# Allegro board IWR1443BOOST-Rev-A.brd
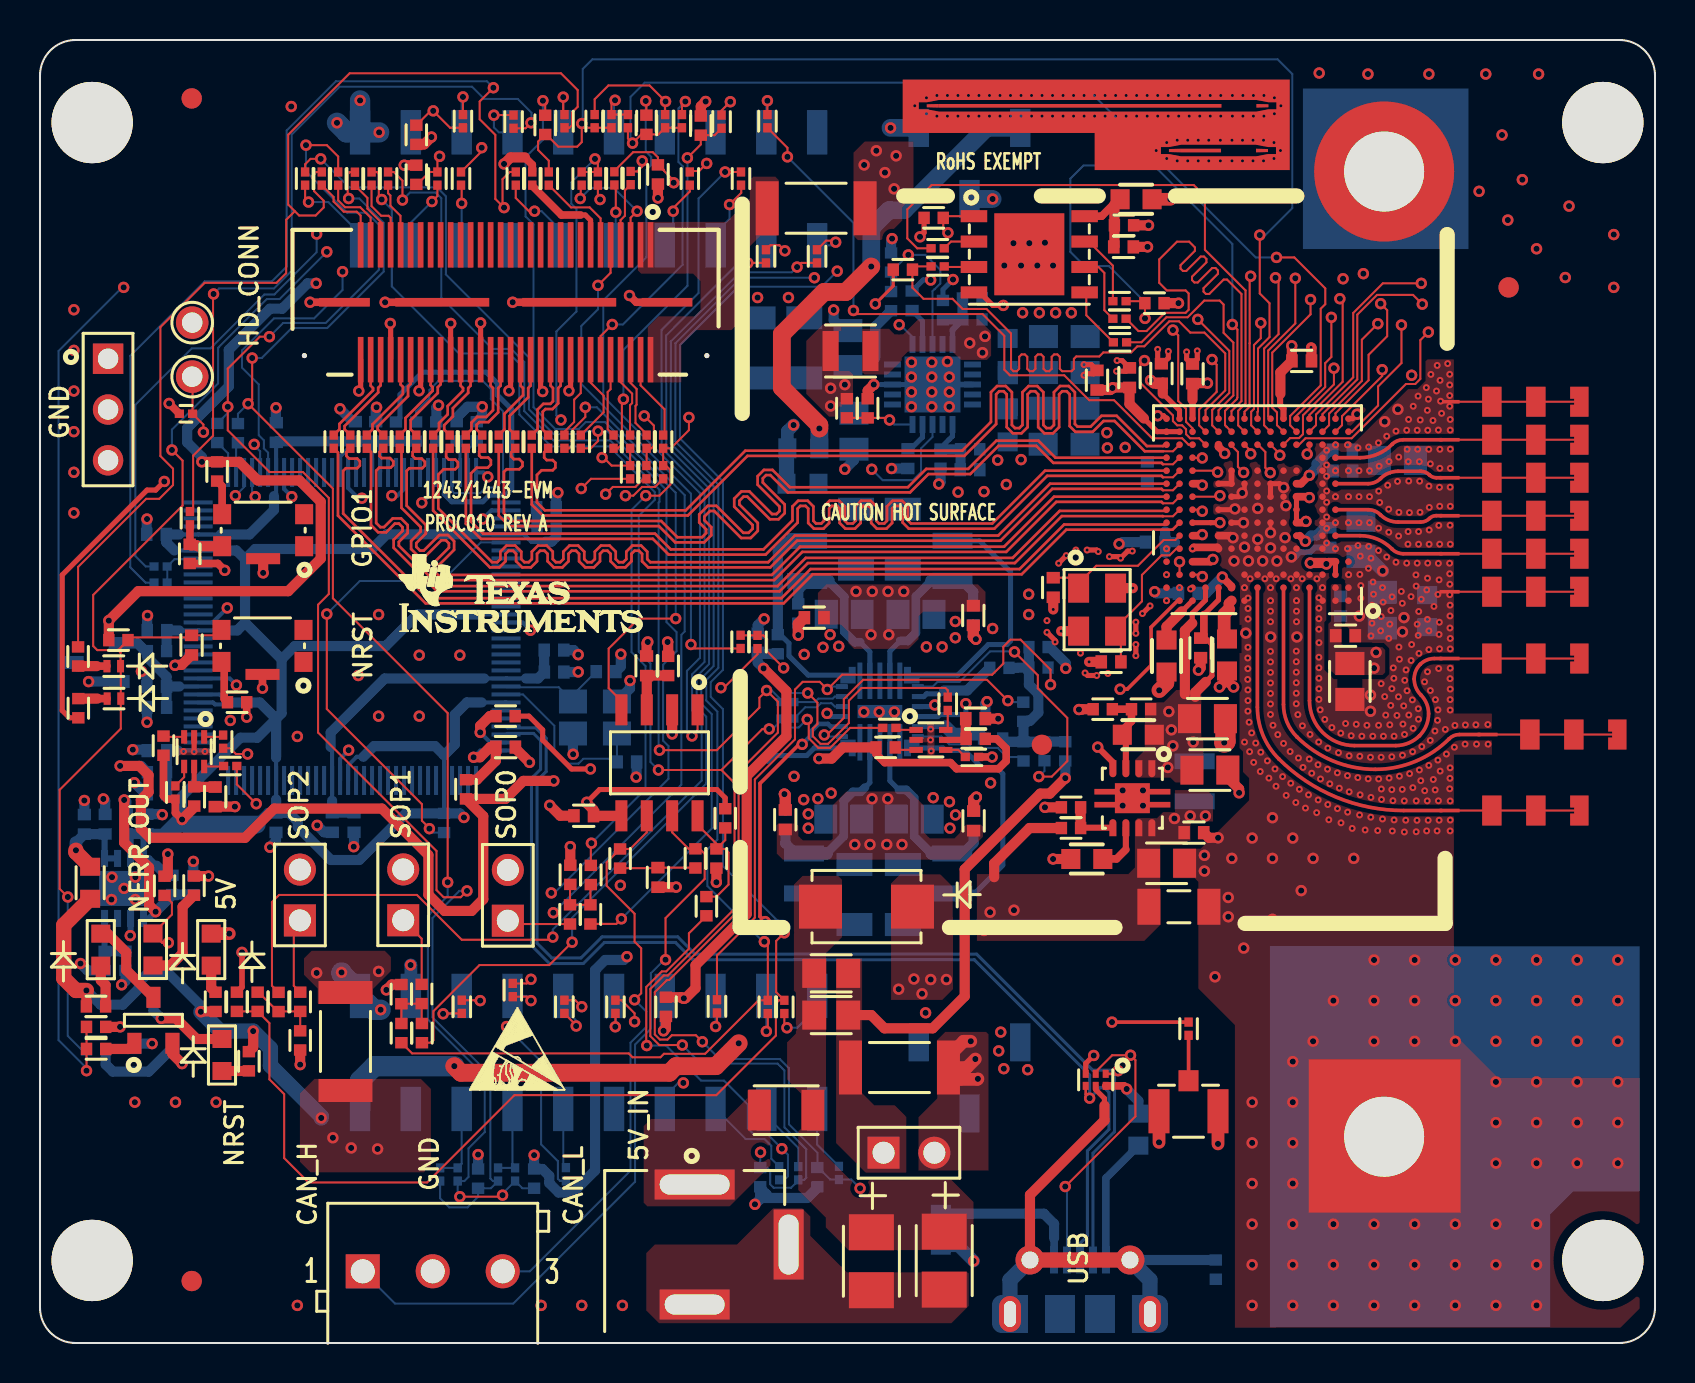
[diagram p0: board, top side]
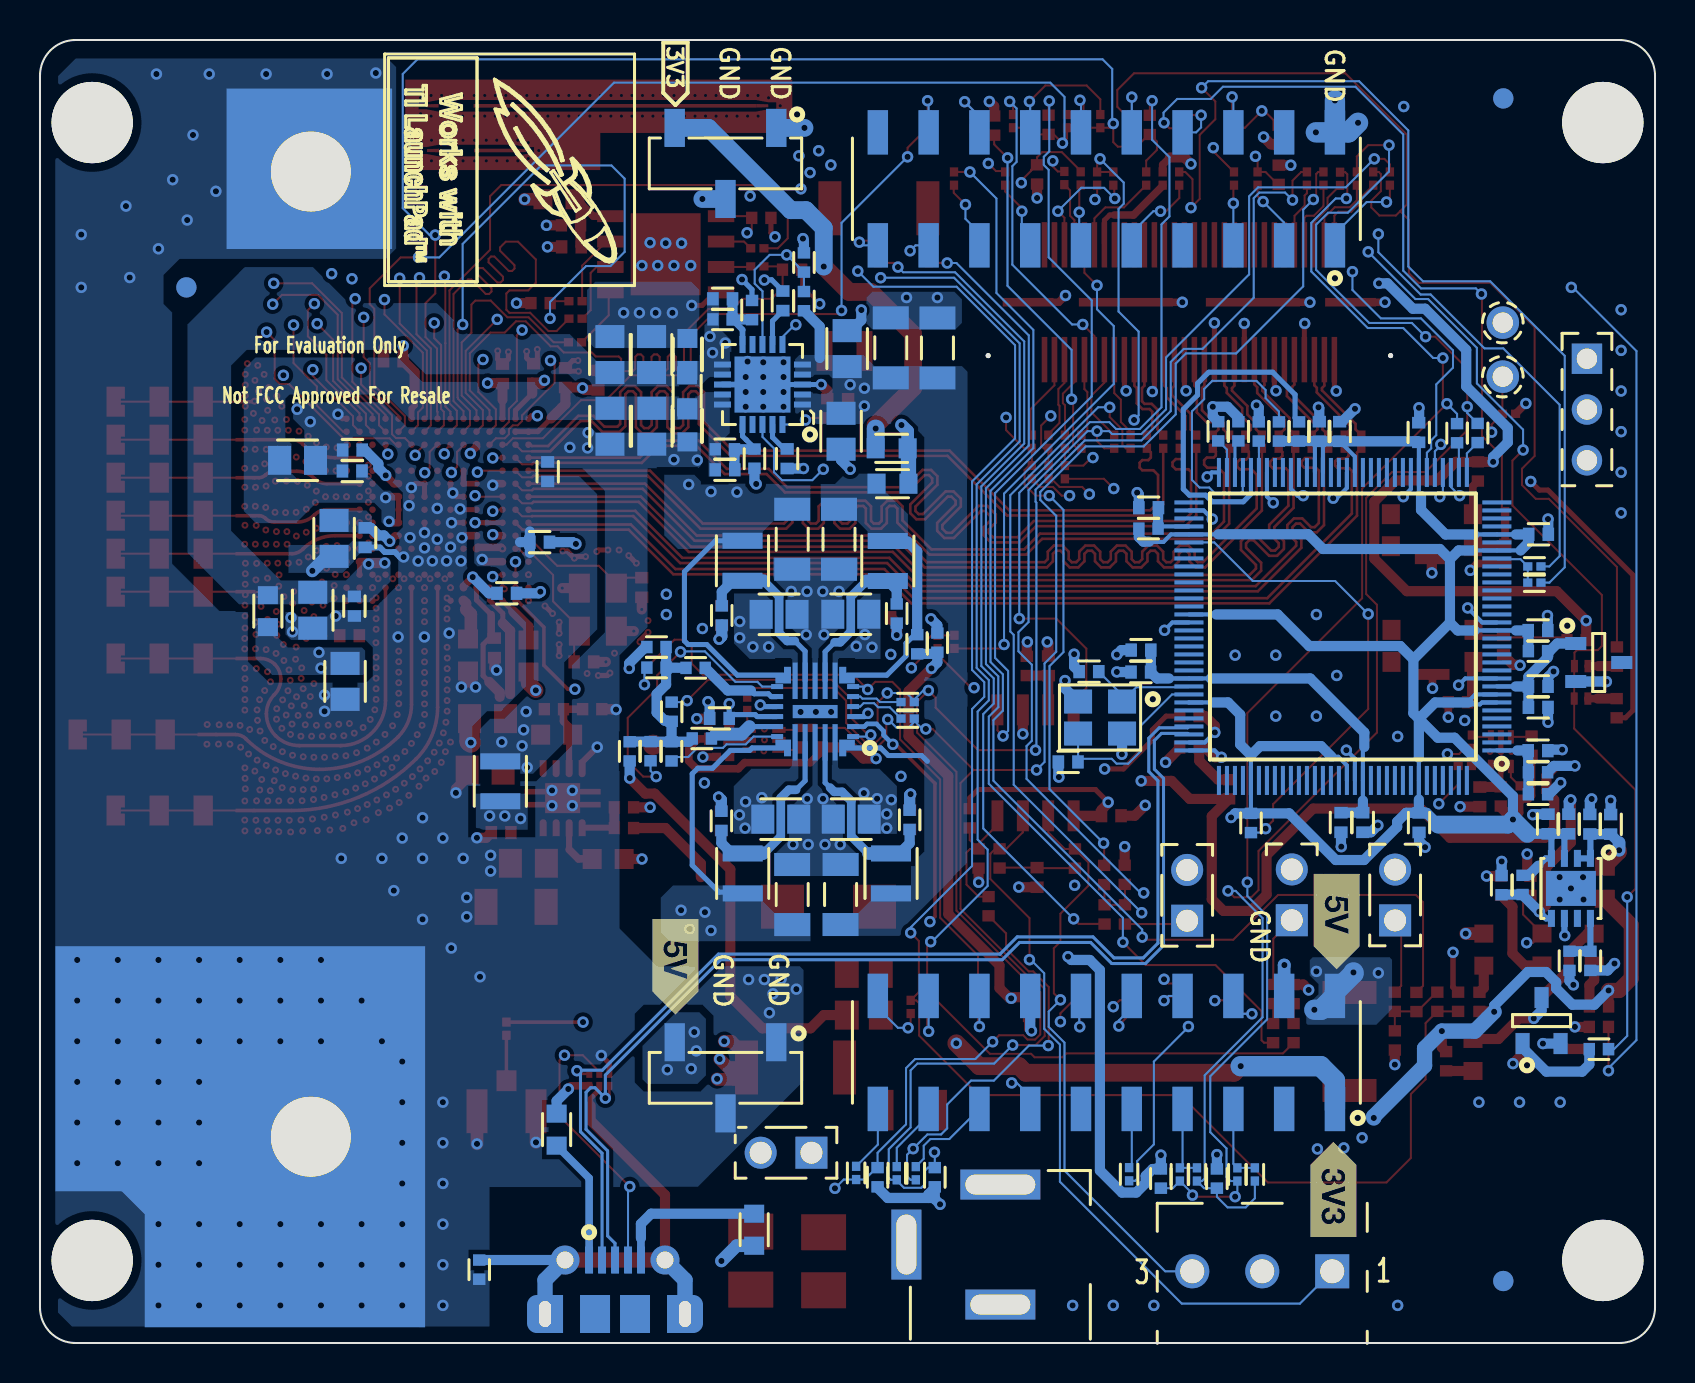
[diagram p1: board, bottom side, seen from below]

Outline 80.77 x 65.15 mm; copper layers: TOP, L2, L3, L4, L5, BOTTOM. Coordinates in mm from the lower left corner of the outline.
Outline path: 0,63.37 0,1.78 arc(0.52,0.52) 1.78,0 78.99,0 arc(80.25,0.52) 80.77,1.78 80.77,63.37 arc(80.25,64.63) 78.99,65.15 1.78,65.15 arc(0.52,64.63) 0,63.37

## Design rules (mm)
constraint set DEFAULT: min track width 0.102
net group DIFFPAIR0: nets AR_LVDS_VALIDM AR_LVDS_VALIDP
net group DIFFPAIR1: nets AR_LVDSCSI_FRCLKM AR_LVDSCSI_FRCLKP
net group DIFFPAIR2: nets AR_LVDSCSI_3M AR_LVDSCSI_3P
net group DIFFPAIR3: nets AR_LVDSCSI_2M AR_LVDSCSI_2P
net group DIFFPAIR4: nets AR_LVDSCSI_CLKM AR_LVDSCSI_CLKP
net group DIFFPAIR5: nets AR_LVDSCSI_1M AR_LVDSCSI_1P
net group DIFFPAIR6: nets AR_LVDSCSI_0M AR_LVDSCSI_0P
net group DIFFPAIR7: nets UNNAMED_6_QSH03001XD_I1_56 UNNAMED_6_QSH03001XD_I1_58
net group DIFFPAIR8: nets UNNAMED_6_QSH03001XD_I1_50 UNNAMED_6_QSH03001XD_I1_52
net group DIFFPAIR9: nets UNNAMED_6_QSH03001XD_I1_44 UNNAMED_6_QSH03001XD_I1_46
net group DIFFPAIR10: nets UNNAMED_6_QSH03001XD_I1_38 UNNAMED_6_QSH03001XD_I1_40
net group DIFFPAIR11: nets UNNAMED_6_QSH03001XD_I1_32 UNNAMED_6_QSH03001XD_I1_34
net group DIFFPAIR12: nets UNNAMED_6_QSH03001XD_I1_26 UNNAMED_6_QSH03001XD_I1_28
net group DIFFPAIR13: nets UNNAMED_6_QSH03001XD_I1_20 UNNAMED_6_QSH03001XD_I1_22
net group DIFFPAIR14: nets XDSET_1_DM XDSET_1_DP

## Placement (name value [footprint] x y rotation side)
C1  -  [CC0603]  54.82 57.19 180 top
C2  -  [CC0402]  54.19 54.81 180 top
C3  -  [CC0402]  63.1 49.11 180 top
C4  -  [CC0402]  56.09 48.48 270 top
C5  -  [CC0402]  57.64 48.46 270 top
C6  -  [CC0402]  54.49 48.27 270 top
C7  -  [CC0402]  52.87 48.14 270 top
C8  -  [CC0201]  7.3 46.46 0 top
C9  -  [CC0402]  50.68 37.78 90 top
C10  -  [CC0402]  65.29 35.37 180 top
C11  -  [CC0402]  7.58 34.89 90 top
C12  -  [CC0402]  58.05 34.75 90 top
C13  -  [CC0603]  59.36 34.4 90 top
C14  -  [CC0603]  56.34 34.35 90 top
C15  -  [CC0402]  53.57 34.06 0 top
C16  -  [CC0402]  30.34 33.86 270 top
C17  -  [CC0805]  58.39 31.22 180 top
C18  -  [CC0603]  54.93 30.41 0 top
C19  -  [CC0805]  58.51 28.65 180 top
C20  -  [CC0402]  27.19 26.36 0 top
C21  -  [CC0402]  57.71 25.52 180 top
C22  -  [CC0603]  52.35 24.2 0 top
C23  -  [CC0805]  56.35 23.99 180 top
C24  -  [CC0402]  30.91 23.28 90 top
C25  -  [CC1206]  56.96 21.81 180 top
C26  -  [CAPMP3528X210N]  45.22 4.12 270 top
C27  -  [CAPMP3528X210N]  41.58 4.09 270 top
C28  -  [CC0402]  46.63 52.21 0 bottom
C29  -  [CC0402]  43.62 52.11 270 bottom
C30  -  [CC1206]  38.22 49.76 270 bottom
C31  -  [CC1206]  35.89 49.75 270 bottom
C32  -  [CC0805]  40.4 49.72 270 bottom
C33  -  [CC0603]  48.39 49.43 270 bottom
C34  -  [CC0805]  52.27 49.42 270 bottom
C35  -  [CC0805]  50.19 49.42 270 bottom
C36  -  [CC0603]  48.39 45.86 90 bottom
C37  -  [CC0805]  50.17 45.84 90 bottom
C38  -  [CC0805]  52.27 45.84 90 bottom
C39  -  [CC0402]  65.15 44.65 180 bottom
C40  -  [CC0805]  40.71 45.59 90 bottom
C41  -  [CC0402]  16.79 45.58 270 bottom
C42  -  [CC0402]  15.77 45.58 270 bottom
C43  -  [CC0402]  11.82 45.53 270 bottom
C44  -  [CC0402]  43.41 44.22 90 bottom
C45  -  [CC0805]  67.89 44.13 0 bottom
C46  -  [CC0402]  46.51 43.66 0 bottom
C47  -  [CC0402]  65.16 43.6 180 bottom
C48  -  [CC0402]  55.38 43.57 270 bottom
C49  -  [CC0402]  25.33 41.77 180 bottom
C50  -  [CC0402]  5.83 40.43 0 bottom
C51  -  [CC0402]  64.51 40.27 90 bottom
C52  -  [CC0805]  66.06 40.23 90 bottom
C53  -  [CC0402]  55.78 40.04 0 bottom
C54  -  [CC1206]  43.15 40.19 90 bottom
C55  -  [CC1206]  40.81 40.19 90 bottom
C56  -  [CC0402]  57.43 37.49 0 bottom
C57  -  [CC0402]  65.05 36.84 90 bottom
C58  -  [CC0805]  67.13 36.64 90 bottom
C59  -  [CC0805]  40.22 36.44 180 bottom
C60  -  [CC0805]  43.81 36.43 0 bottom
C61  -  [CC0402]  5.85 35.63 0 bottom
C62  -  [CC0402]  25.71 34.65 180 bottom
C63  -  [CC0402]  28.31 33.57 180 bottom
C64  -  [CC0402]  25.71 33.55 180 bottom
C65  -  [CC0805]  65.52 33.08 90 bottom
C66  -  [CC0402]  5.84 32.83 0 bottom
C67  -  [CC0402]  5.84 31.78 0 bottom
C68  -  [CC0402]  46.79 31.23 180 bottom
C69  -  [CC0402]  5.85 29.62 0 bottom
C70  -  [CC0402]  29.35 29.06 180 bottom
C71  -  [CC0402]  23.29 29.79 180 top
C72  -  [CC0805]  43.72 26.19 0 bottom
C73  -  [CC0805]  40.2 26.19 180 bottom
C74  -  [CC0402]  15.71 26.03 90 bottom
C75  -  [CC0402]  14.62 26.03 90 bottom
C76  -  [CC0402]  11.8 26.02 90 bottom
C77  -  [CC0402]  5.35 25.95 270 bottom
C78  -  [CC0402]  4.31 25.95 270 bottom
C79  -  [CC0402]  3.26 25.94 270 bottom
C80  -  [CC0402]  2.22 25.93 270 bottom
C81  -  [CC1206]  40.73 22.43 270 bottom
C82  -  [CC1206]  43.15 22.42 270 bottom
C83  -  [CC0805]  65.51 33.07 90 top
C84  -  [CC0402]  46.79 31.22 180 top
C85  -  [CC0402]  8.76 27.31 90 top
C86  -  [CC0402]  38.72 36.27 180 top
C87  -  [CC0402]  46.68 36.38 270 top
C88  -  [CC0402]  37.27 26.17 90 top
C89  -  [CC0402]  46.69 26.11 90 top
D1  -  [DFN100X60X50-2N]  3.69 33.84 0 top
D2  -  [DFN100X60X50-2N]  3.7 32.22 0 top
D3  -  [DIOM5436X295N]  41.34 21.82 0 top
DS1  -  [LED0603]  5.65 19.68 270 top
DS2  -  [LED0603]  8.56 19.67 270 top
DS3  -  [LED0603]  3.04 19.67 270 top
DS4  -  [LED0603]  9.1 14.4 270 top
F1  -  [FUSE1206]  37.32 11.64 0 top
FB1  -  [FB0805]  39.57 16.4 0 top
FB2  -  [FB0805]  39.57 18.48 0 top
J1  -  [SAMTEC_QSH-030-01-X-D-A]  23.29 52.04 180 top
J2  -  [CINCH_128-0711-201]  57.44 11.59 90 top
J3  -  [OST_OSTTE030161]  16.14 3.59 0 top
J4  -  [SAMTEC_SSM-103-XX-SV]  46.49 58.98 0 bottom
J5  -  [SAMTEC_SSM-110-XX-DV]  27.44 57.71 180 bottom
J6  -  [SAMTEC_SSM-110-XX-DV]  27.44 14.53 180 bottom
J7  -  [SAMTEC_SSM-103-XX-SV]  46.49 13.26 0 bottom
J8  -  [MOLEX_105017-0001]  52.01 1.6 180 bottom
L1  -  [INDC2520X120N]  45.64 39.11 90 bottom
L2  -  [INDC2520X120N]  38.37 39.1 270 bottom
L3  -  [INDC2520X120N]  45.63 23.48 270 bottom
L4  -  [INDC2520X120N]  38.21 23.48 90 bottom
L5  -  [INDC2520X120N]  40.54 49.6 0 top
L6  -  [INDC2520X120N]  57.75 28.09 90 bottom
NOREF  -  []  3.19 33.54 0 top
NOREF#2  -  []  14.74 60.25 0 top
NOREF#3  -  []  46.64 46.93 90 top
NOREF#4  -  []  8.61 28.83 90 top
NOREF#5  -  []  7.13 15.46 90 top
NOREF#6  -  []  48.51 1.45 90 top
NOREF#7  -  []  8.16 18.87 0 top
NOREF#8  -  []  39.04 21.82 0 top
NOREF#9  -  []  55.69 46.87 0 top
NOREF#10  -  []  52.66 4.15 0 top
NOREF#11  -  []  43.95 60.76 0 top
NOREF#12  -  []  6.62 14.99 90 top
NOREF#13  -  []  4.72 14.97 0 top
NOREF#14  -  []  8.39 48.54 0 top
NOREF#15  -  []  12.63 48.42 0 top
NOREF#16  -  []  53.66 25.77 90 top
NOREF#17  -  []  8.61 42.83 0 top
NOREF#18  -  []  3.04 18.87 90 top
NOREF#19  -  []  3.36 32.22 0 top
NOREF#20  -  []  37.21 22.23 90 top
NOREF#21  -  []  26.15 30.02 90 top
NOREF#22  -  [unnamed#2]  67.23 58.57 0 top
NOREF#23  -  []  5.65 18.88 90 top
NOREF#24  -  []  14.74 55.17 90 top
NOREF#25  -  []  5.18 21.23 90 top
NOREF#26  -  []  36.33 11.7 0 top
NOREF#27  -  []  43.64 49.93 0 top
NOREF#28  -  []  2.64 18.87 0 top
NOREF#29  -  []  4.21 16.8 0 top
NOREF#30  -  [unnamed#3]  78.16 61.02 0 top
NOREF#31  -  []  39.37 40.35 90 top
NOREF#32  -  []  3.23 24.23 0 top
NOREF#33  -  []  8.39 51.25 0 top
NOREF#34  -  []  14.74 11.99 90 top
NOREF#35  -  []  15.23 52.04 0 top
NOREF#36  -  [unnamed#2]  50.11 29.91 0 top
NOREF#37  -  []  3.44 18.87 90 top
NOREF#38  -  []  40.92 8.24 0 top
NOREF#39  -  []  18.17 21.14 90 top
NOREF#40  -  []  52.08 12.66 0 top
NOREF#41  -  []  42.68 11.99 0 top
NOREF#42  -  []  55.76 -1.1 90 top
NOREF#43  -  []  6.05 18.88 90 top
NOREF#44  -  []  41.01 30.03 0 top
NOREF#45  -  []  38.21 22.48 90 top
NOREF#46  -  [unnamed#3]  2.61 61.02 0 top
NOREF#47  -  [unnamed#2]  73.45 52.78 0 top
NOREF#48  -  [unnamed#3]  78.16 4.13 0 top
NOREF#49  -  []  8.56 18.87 90 top
NOREF#50  -  []  54.96 28.72 0 top
NOREF#51  -  []  4.19 33.54 90 top
NOREF#52  -  []  9.08 34.06 90 top
NOREF#53  -  []  2.71 21.23 90 top
NOREF#54  -  []  5.67 17.29 0 top
NOREF#55  -  []  46.63 22.23 90 top
NOREF#56  -  []  8.7 13.6 0 top
NOREF#57  -  []  13.22 49.37 0 top
NOREF#58  -  [unnamed#2]  67.23 10.31 0 top
NOREF#59  -  []  37.37 42.85 0 top
NOREF#60  -  []  41.79 48.6 90 top
NOREF#61  -  []  9.11 39.84 0 top
NOREF#62  -  []  16.04 49.17 0 top
NOREF#63  -  []  44.64 40.36 0 top
NOREF#64  -  []  16.04 49.17 90 top
NOREF#65  -  []  19.44 19.87 90 top
NOREF#66  -  []  9.5 13.6 90 top
NOREF#67  -  []  23.31 32.03 90 top
NOREF#68  -  []  39.29 48.6 0 top
NOREF#69  -  []  28.24 -5.78 0 top
NOREF#70  -  []  46.63 53.8 90 top
NOREF#71  -  []  44.06 20.01 90 top
NOREF#72  -  []  52.48 51.94 90 top
NOREF#73  -  []  3.4 46.67 90 top
NOREF#74  -  []  9.08 34.06 0 top
NOREF#75  -  [unnamed#3]  2.61 4.13 0 top
NOREF#76  -  []  44.64 37.86 90 top
NOREF#77  -  []  33.94 48.42 90 top
NOREF#78  -  []  38.61 20.01 0 top
NOREF#79  -  []  4.21 15.47 90 top
NOREF#80  -  []  56.75 26.84 90 top
NOREF#81  -  []  32.74 7.92 0 top
NOREF#82  -  []  26.65 32.07 0 top
NOREF#83  -  []  4.2 31.92 90 top
NOREF#84  -  []  38.37 38.1 90 top
NOREF#85  -  []  3.2 31.92 0 top
NOREF#86  -  []  50.3 11.99 90 top
NOREF#87  -  []  56.75 29.34 0 top
NOREF#88  -  []  40.01 33.82 0 top
NOREF#89  -  []  55.97 11.59 0 top
NOREF#90  -  []  14.27 19.86 90 top
NOREF#91  -  []  2.16 42.86 90 top
NOREF#92  -  []  4.72 14.97 90 top
NOREF#93  -  []  3.35 33.84 0 top
NOREF#94  -  []  55.69 36.47 90 top
NOREF#95  -  []  22.13 19.84 0 top
NOREF#96  -  []  42.19 9.51 0 top
NOREF#97  -  []  24.67 19.84 90 top
NOREF#98  -  []  46.63 52.53 0 top
NOREF#99  -  []  9.06 42.04 0 top
NOREF#100  -  []  45.63 22.48 90 top
NOREF#101  -  []  13 21.13 90 top
NOREF#102  -  []  0 63.37 0 top
NOREF#103  -  []  11.73 19.86 0 top
NOREF#104  -  []  55.94 10.29 90 top
NOREF#105  -  []  52.8 12.86 0 top
NOREF#106  -  []  56.13 25.74 90 top
NOREF#107  -  []  42.64 53.93 0 top
NOREF#108  -  []  39.54 49.6 0 top
NOREF#109  -  []  51.62 38.27 0 top
NOREF#110  -  []  50.3 57.71 90 top
NOREF#111  -  []  40.01 33.82 90 top
NOREF#112  -  []  37.24 -5.78 90 top
NOREF#113  -  []  54.12 35.07 90 top
NOREF#114  -  []  9.1 13.6 90 top
NOREF#115  -  []  23.4 21.11 90 top
NOREF#116  -  []  4.21 16.78 0 top
NOREF#117  -  []  2.16 50.48 0 top
NOREF#118  -  []  37.21 24.73 0 top
NOREF#119  -  []  78.99 0 90 top
NOREF#120  -  []  24.54 54.91 0 top
NOREF#121  -  []  36.33 54.88 0 top
NOREF#122  -  []  57.75 27.09 90 top
NOREF#123  -  []  55.94 12.89 0 top
NOREF#124  -  []  42.68 57.71 0 top
NOREF#125  -  []  43.95 15.04 0 top
NOREF#126  -  []  24.89 -0.01 90 top
NOREF#127  -  []  32.74 1.92 90 top
NOREF#128  -  []  26.15 30.02 0 top
NOREF#129  -  []  44.63 22.23 0 top
NOREF#130  -  []  45.64 38.11 90 top
NOREF#131  -  []  40.92 8.24 90 top
NOREF#132  -  []  52.08 13.66 0 top
NOREF#133  -  []  42.64 49.93 90 top
NOREF#134  -  []  5.25 18.88 0 top
NOREF#135  -  []  9.11 39.84 90 top
NOREF#136  -  []  16.9 19.87 0 top
NOREF#137  -  [unnamed#2]  7.59 3.1 0 top
NOREF#138  -  []  65.44 39.07 90 top
NOREF#139  -  []  51.94 35.59 90 top
NOREF#140  -  [unnamed#2]  7.59 62.23 0 top
NOREF#141  -  []  43.6 29.75 90 top
NOREF#142  -  []  13.23 30.66 0 top
NOREF#143  -  []  14.74 17.07 0 top
NOREF#144  -  []  19.64 3.59 0 top
NOREF#145  -  []  8.96 18.87 90 top
NOREF#146  -  []  48.51 1.45 0 top
NOREF#147  -  [unnamed#2]  73.45 52.78 180 bottom
NOREF#148  -  [unnamed#2]  7.59 3.1 180 bottom
NOREF#149  -  [unnamed#2]  7.59 62.23 180 bottom
P1  -  [MOLEX_22-28-4033]  3.4 49.21 0 top
P2  -  [MULTICOMP_2211S-02G]  18.17 21.14 90 top
P3  -  [MULTICOMP_2211S-02G]  13 21.13 90 top
P4  -  [MULTICOMP_2211S-02G]  23.4 21.11 90 top
P5  -  [MULTICOMP_2211S-02G]  42.19 9.51 0 top
P6  -  [CUI_PJ-002AH]  32.74 7.92 0 top
Q1  -  [SOT95P240X120-3N]  5.67 16.14 90 top
Q2  -  [SOT95P240X120-3N]  5.67 16.12 90 bottom
R1  -  [RC0201]  21.15 61.09 270 top
R2  -  [RC0201]  26.23 61.09 270 top
R3  -  [RC0201]  27.74 61.09 270 top
R4  -  [RC0201]  28.58 61.09 270 top
R5  -  [RC0201]  29.4 61.09 270 top
R6  -  [RC0201]  31.26 61.09 270 top
R7  -  [RC0201]  32.11 61.09 270 top
R8  -  [RC0201]  36.38 61.09 270 top
R9  -  [RC0201]  23.69 61.07 270 top
R10  -  [RC0201]  34.09 61.07 270 top
R11  -  [RC0402]  30.33 60.91 90 top
R12  -  [RC0402]  25.27 60.91 90 top
R13  -  [RC0402]  33.05 60.87 270 top
R14  -  [RC0402]  18.82 60.41 270 top
R15  -  [RC0402]  30.91 58.43 270 top
R16  -  [RC0402]  18.82 58.41 90 top
R17  -  [RC0201]  29.54 58.25 270 top
R18  -  [RC0201]  28.73 58.23 270 top
R19  -  [RC0201]  13.26 58.22 270 top
R20  -  [RC0201]  14.09 58.22 270 top
R21  -  [RC0201]  14.91 58.22 270 top
R22  -  [RC0201]  16.58 58.22 270 top
R23  -  [RC0201]  17.41 58.22 270 top
R24  -  [RC0201]  19.88 58.22 270 top
R25  -  [RC0201]  21.06 58.22 270 top
R26  -  [RC0201]  23.8 58.22 270 top
R27  -  [RC0201]  24.62 58.22 270 top
R28  -  [RC0201]  25.45 58.22 270 top
R29  -  [RC0201]  27.09 58.22 270 top
R30  -  [RC0201]  27.9 58.22 270 top
R31  -  [RC0201]  32.5 58.22 270 top
R32  -  [RC0201]  35.06 58.22 270 top
R33  -  [RC0201]  15.75 58.21 270 top
R34  -  [RC2010]  38.82 56.74 0 top
R35  -  [RC0201]  36.31 54.34 90 top
R36  -  [RC0201]  38.86 54.34 90 top
R37  -  [RC0402]  54.22 55.89 0 top
R38  -  [RC0402]  44.7 56.26 180 top
R39  -  [RC0201]  44.9 54.74 0 top
R40  -  [RC0201]  53.99 52.09 0 top
R41  -  [RC0402]  55.74 51.99 0 top
R42  -  [RC0201]  44.9 53.83 0 top
R43  -  [RC0402]  43.16 53.67 180 top
R44  -  [RC0201]  53.99 51.22 0 top
R45  -  [RC0201]  54.01 50.03 0 top
R46  -  [RC0402]  40.36 46.74 270 top
R47  -  [RC0402]  41.4 46.74 90 top
R48  -  [RC0201]  14.69 45.07 270 top
R49  -  [RC0201]  15.52 45.07 270 top
R50  -  [RC0201]  16.34 45.07 270 top
R51  -  [RC0201]  17.17 45.07 270 top
R52  -  [RC0201]  18 45.07 270 top
R53  -  [RC0201]  18.82 45.07 270 top
R54  -  [RC0201]  19.66 45.07 270 top
R55  -  [RC0201]  20.49 45.07 270 top
R56  -  [RC0201]  21.3 45.07 270 top
R57  -  [RC0201]  22.12 45.07 270 top
R58  -  [RC0201]  22.94 45.07 270 top
R59  -  [RC0201]  23.77 45.07 270 top
R60  -  [RC0201]  24.59 45.07 270 top
R61  -  [RC0201]  25.41 45.07 270 top
R62  -  [RC0201]  26.23 45.07 270 top
R63  -  [RC0201]  27.05 45.07 270 top
R64  -  [RC0201]  28.69 45.07 270 top
R65  -  [RC0201]  29.51 45.07 270 top
R66  -  [RC0201]  30.34 45.07 270 top
R67  -  [RC0201]  31.17 45.07 270 top
R68  -  [RC0402]  8.86 43.58 90 top
R69  -  [RC0201]  29.51 43.54 270 top
R70  -  [RC0201]  30.33 43.54 270 top
R71  -  [RC0201]  31.17 43.54 270 top
R72  -  [RC0201]  7.5 41.24 90 top
R73  -  [RC0402]  7.49 39.46 90 top
R74  -  [RC0402]  3.92 35.14 180 top
R75  -  [RC0201]  35.04 35.06 270 top
R76  -  [RC0201]  35.88 35.05 270 top
R77  -  [RC0402]  1.91 34.32 270 top
R78  -  [RC0402]  31.42 33.85 90 top
R79  -  [RC0402]  9.86 32.04 180 top
R80  -  [RC0402]  1.92 31.74 90 top
R81  -  [RC0402]  53.15 31.69 0 top
R82  -  [RC0402]  55.07 31.69 0 top
R83  -  [RC0402]  51.56 26.78 180 top
R84  -  [RC0402]  51.56 25.75 0 top
R85  -  [RC0402]  32.78 24.23 90 top
R86  -  [RC0402]  33.83 24.22 270 top
R87  -  [RC0402]  29.01 24.22 270 top
R88  -  [RC0402]  26.52 23.41 270 top
R89  -  [RC0402]  27.55 23.4 270 top
R90  -  [RC0402_40]  7.7 22.87 90 top
R91  -  [RC0402]  6.23 22.86 90 top
R92  -  [RC0402]  26.51 21.43 270 top
R93  -  [RC0402]  27.53 21.43 270 top
R94  -  [RC0201]  23.65 17.65 90 top
R95  -  [RC0402]  19.09 17.45 90 top
R96  -  [RC0402]  18.07 17.44 270 top
R97  -  [RC0402]  9.85 17.06 90 top
R98  -  [RC0402]  10.89 17.06 90 top
R99  -  [RC0402]  13.01 17.06 90 top
R100  -  [RC0402]  8.78 17.06 270 top
R101  -  [RC0402]  11.93 17.05 90 top
R102  -  [RC0201]  33.86 16.83 90 top
R103  -  [RC0402]  2.8 16.83 180 top
R104  -  [RC0201]  21.09 16.81 90 top
R105  -  [RC0201]  26.23 16.81 90 top
R106  -  [RC0201]  28.78 16.81 90 top
R107  -  [RC0402]  31.31 16.81 90 top
R108  -  [RC0201]  36.4 16.8 90 top
R109  -  [RC0201]  37.23 16.8 90 top
R110  -  [RC0402]  2.81 15.81 180 top
R111  -  [RC0201]  57.44 15.71 270 top
R112  -  [RC0402]  19.1 15.5 270 top
R113  -  [RC0402]  18.08 15.5 90 top
R114  -  [RC0402]  13.01 15.13 90 top
R115  -  [RC2010]  15.28 15.08 270 top
R116  -  [RC0402]  2.81 14.7 0 top
R117  -  [RC0402]  10.45 14.09 90 top
R118  -  [RC2010]  42.98 13.77 0 top
R119  -  [RC0402]  42.56 54.03 270 bottom
R120  -  [RC0402]  42.56 52.1 270 bottom
R121  -  [RC0402]  45.16 51.65 270 bottom
R122  -  [RC0402]  46.64 51.18 0 bottom
R123  -  [RC0402]  21.84 45.58 90 bottom
R124  -  [RC0402]  18.81 45.58 270 bottom
R125  -  [RC0402]  19.82 45.58 270 bottom
R126  -  [RC0402]  20.84 45.58 90 bottom
R127  -  [RC0402]  17.8 45.58 270 bottom
R128  -  [RC0402]  8.87 45.5 270 bottom
R129  -  [RC0402]  9.9 45.49 270 bottom
R130  -  [RC0603]  38.18 44.73 180 bottom
R131  -  [RC0402]  46.52 44.69 0 bottom
R132  -  [RC0402]  45.04 44.22 90 bottom
R133  -  [RC0603]  38.14 42.97 180 bottom
R134  -  [RC0402]  25.33 40.72 0 bottom
R135  -  [RC0201]  6.03 38.83 0 bottom
R136  -  [RC0201]  6.03 38.02 0 bottom
R137  -  [RC0603]  69.38 36.59 270 bottom
R138  -  [RC0402]  35.89 35.02 270 bottom
R139  -  [RC0402]  49.94 34.8 180 bottom
R140  -  [RC0402]  5.85 34.6 0 bottom
R141  -  [RC0402]  36.9 34.94 270 bottom
R142  -  [RC0402]  49.94 33.77 180 bottom
R143  -  [RC0402]  47.98 33.76 0 bottom
R144  -  [RC0201]  37.38 32.05 0 bottom
R145  -  [RC0402]  49.18 31.56 270 bottom
R146  -  [RC0201]  37.38 31.22 0 bottom
R147  -  [RC0402]  47.67 30.23 0 bottom
R148  -  [RC0402]  50.23 29.59 90 bottom
R149  -  [RC0402]  51.28 29.58 270 bottom
R150  -  [RC0402]  49.19 29.58 270 bottom
R151  -  [RC0402]  5.85 28.54 0 bottom
R152  -  [RC0402]  23.29 31.34 0 top
R153  -  [RC0402]  5.85 27.44 0 bottom
R154  -  [RC0402]  21.3 27.69 270 top
R155  -  [RC0402]  20.21 26 90 bottom
R156  -  [RC0402]  6.62 22.9 90 bottom
R157  -  [RC0402_40]  7.67 22.89 270 bottom
R158  -  [RC0402]  4.28 19.11 90 bottom
R159  -  [RC0402]  3.23 19.11 90 bottom
R160  -  [RC0402]  2.81 14.69 0 bottom
R161  -  [RC0603]  54.93 10.67 90 bottom
R162  -  [RC0201]  39.95 8.5 90 bottom
R163  -  [RC0201]  37.92 8.49 90 bottom
R164  -  [RC0201]  36.97 8.49 90 bottom
R165  -  [RC0201]  26.3 8.44 90 bottom
R166  -  [RC0201]  23.76 8.43 90 bottom
R167  -  [RC0201]  22.91 8.43 90 bottom
R168  -  [RC0201]  20.89 8.43 90 bottom
R169  -  [RC0201]  20.01 8.43 90 bottom
R170  -  [RC0402]  38.88 8.29 270 bottom
R171  -  [RC0402]  36.02 8.29 270 bottom
R172  -  [RC0402]  24.71 8.22 90 bottom
R173  -  [RC0402]  21.91 8.22 90 bottom
R174  -  [RC0402_40]  58.8 3.67 90 bottom
R175  -  [RC0603]  45.05 5.66 90 bottom
R176  -  [RC0603]  2.51 23.01 270 top
R177  -  [RC0402]  33.33 21.84 270 top
R178  -  [RC0402]  34.27 26.23 270 top
R179  -  [RC0402]  42.29 29.78 180 top
R180  -  [RC0201]  42.48 30.76 0 top
R181  -  [RC0201]  46.61 29.3 180 top
R182  -  [RC0201]  45.4 31.96 90 top
R183  -  [RC0402]  46.8 30.21 0 top
R184  -  [RC0402]  6.18 29.87 270 top
R185  -  [RC0201]  9.16 30.07 90 top
R186  -  [RC0201]  9.51 28.85 0 top
R187  -  [RC0402]  7.71 27.33 270 top
R188  -  [RC0201]  6.77 27.53 270 top
R189  -  [RC0603]  48.41 47.59 270 bottom
R190  -  [RC0402]  37.92 36.47 90 bottom
R191  -  [RC0402]  46.67 36.38 90 bottom
R192  -  [RC0402]  37.28 26.16 270 bottom
R193  -  [RC0402]  46.69 26.11 270 bottom
SW1  -  [SW_KMR2XXG]  11.16 40.64 180 top
SW2  -  [SW_KMR2XXG]  11.13 34.86 180 top
TP1  -  [TP_C163H102]  7.61 51.02 0 top
TP2  -  [TP_C163H102]  7.61 48.32 0 top
U1  -  [SON127P600X500X80_EPA-9N]  49.48 54.44 0 top
U2  -  [BGA161C65P15X15_1040X1040X120]  60.89 41.67 180 top
U3  -  [SOIC127P600X175-8N]  30.98 29.01 270 top
U4  -  [SON65P300X300X100-9]  54.63 27.24 270 top
U5  -  [QFN50P400X400X80_EPE-21N]  44.64 47.93 0 bottom
U6  -  [QFP40P1600X1600X120-128N]  15.61 35.83 0 bottom
U7  -  [SOT95P237X112-3N]  2.82 34.03 180 bottom
U8  -  [P87524BRNFRQ1_ES2_2_PRELIMINARY]  42.01 31.57 0 bottom
U9  -  [SON65P300X300X100_EPA-9N]  4.21 22.73 270 bottom
U10  -  [PSON50P100X145X60-6N]  52.8 13.16 270 top
U11  -  [SOTFL50P160X60-6N]  44.56 30.16 0 top
U12  -  [SOTFL50P160X60-6N]  7.71 29.57 270 top
Y1  -  [XTAL_CX3225SA]  52.87 36.67 270 top
Y2  -  [XTAL_NX3225SA]  27.75 31.27 0 bottom

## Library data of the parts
C1 C13 C14 C33 C36 = CAP_NON_POLARIZED: alternate symbols: (); part number: CAP_NON_POLARIZED_0603-GCM188R71C105KA64,1UF,10%
C2 C21 = CAP_NON_POLARIZED: alternate symbols: (); part number: CAP_NON_POLARIZED_0402-CGA2B3X7R1H104K050BB,0.1UF,10%
C3 C5 C7 C10 C12 C39 C47 C48 C51 C53 C56 C57 C68 = CAP_NON_POLARIZED: alternate symbols: (); part number: CAP_NON_POLARIZED_0402-GCM155R71C224KE02,0.22UF,10%
C4 C6 C11 = CAP_NON_POLARIZED: alternate symbols: (); part number: CAP_NON_POLARIZED_0402-GCM155R71C104KA55,0.1UF,10%
C8 = CAP_NON_POLARIZED: alternate symbols: (); part number: CAP_NON_POLARIZED_0201-C0603X7S1A104K030BC,0.1UF,10%
C9 C15 C24 = CAP_NON_POLARIZED: alternate symbols: (); part number: CAP_NON_POLARIZED_0402-GJM1555C1H4R7BB01,4.7PF,+/-0.1PF
C16 C20 C42 C43 C49 C64 C67 C71 C75 C76 C79 C84 C85 = CAP_NON_POLARIZED: alternate symbols: (); part number: CAP_NON_POLARIZED_0402-C0402C104K8RAC,0.1UF,10%
C17 C19 C23 C32 C34 C35 C37 C38 C40 C45 C52 C58-C60 C65 C72 C73 C83 = CAP_NON_POLARIZED: alternate symbols: (CAP_GC_21); part number: CAP_NON_POLARIZED_0805-GCM21BR71A106KE22,10UF,10%
C18 C22 = CAP_NON_POLARIZED: alternate symbols: (); part number: CAP_NON_POLARIZED_0603-GCM188R71C474KA55,0.47UF,10%
C25 C30 C31 = CAP_NON_POLARIZED: alternate symbols: (); part number: CAP_NON_POLARIZED_1206-CGA5L1X7R0J226M160AC,22UF,20%
C26 C27 = CAP_POLARIZED: alternate symbols: (); part number: CAP_POLARIZED_3528-21-T491B476K010AT,47UF,10%
C28 C29 C44 C46 = CAP_NON_POLARIZED: alternate symbols: (); part number: CAP_NON_POLARIZED_0402-CGA2B3X8R1H103K050BB,0.01UF,10%
C41 C61 C62 = CAP_NON_POLARIZED: alternate symbols: (); part number: CAP_NON_POLARIZED_0402-C1005X7S0J105M050BC,1UF,20%
C50 = CAP_NON_POLARIZED: alternate symbols: (); part number: CAP_NON_POLARIZED_0402-C1005X7R1E103K,10NF,10%
C54 C55 C81 C82 = CAP_NON_POLARIZED: alternate symbols: (CAP_GC_31); part number: CAP_NON_POLARIZED_1206-GCM31CR71A226KE02,22UF,10%
C63 C70 = CAP_NON_POLARIZED: alternate symbols: (); part number: CAP_NON_POLARIZED_0402-GRM1555C1H8R0DA01,8PF,+/-0.5PF
C66 C69 = CAP_NON_POLARIZED: alternate symbols: (); part number: CAP_NON_POLARIZED_0402-C0402C103K4RAC,0.01UF,10%
C74 C77 C80 = CAP_NON_POLARIZED: alternate symbols: (); part number: CAP_NON_POLARIZED_0402-C1005X7S1A225K050BC,2.2UF,10%
C78 = CAP_NON_POLARIZED: alternate symbols: (); part number: CAP_NON_POLARIZED_0402-04025A150FAT2A,15PF,1%
C86-C89 = CAP_NON_POLARIZED: alternate symbols: (); part number: CAP_NON_POLARIZED_0402-CGA2B2NP01H391J050BA,390PF,5%
D1 D2 = DIODE_SCHOTTKY: alternate symbols: (); part number: DIODE_SCHOTTKY_2-PIN-SMS3923-040LF
D3 = DIODE_ZENER: alternate symbols: (); part number: DIODE_ZENER_DO-214AA-P6SMB6.8AT3G
DS1 DS2 = LEDS: alternate symbols: (); part number: LEDS_0603-TLMS1000
DS3 DS4 = LEDS: alternate symbols: (); part number: LEDS_0603-TLMY1000
F1 = FUSE: alternate symbols: (); part number: FUSE_1206-0440005.
FB1 FB2 = FERRITE_BEAD: alternate symbols: (); part number: FERRITE_BEAD_0805-BLM21PG300SH1,30 OHM,0%
J1 = QSH_030_01_X_D: alternate symbols: (); part number: QSH_030_01_X_D_CONN-60P-FULL-QSH-030-01-L-D-A
J2 = 128_0711_201: alternate symbols: (); part number: 128_0711_201_SMA-3P-128-0711-201
J3 = OSTTE030161: alternate symbols: (); part number: OSTTE030161_CONN-3P-OSTTE030161
J4 J7 = SSM_103_XX_SV: alternate symbols: (); part number: SSM_103_XX_SV_CONN-3P-SSM-103-S-SV
J5 J6 = SSM_110_XX_DV: alternate symbols: (); part number: SSM_110_XX_DV_CONN-20P-SSM-110-S-DV
J8 = 105017_0001: alternate symbols: (); part number: 105017_0001_CONN-5P-105017-0001
L1-L6 = INDUCTOR: alternate symbols: (); part number: INDUCTOR_1008-DFE252012P-R47M,0.47UH,20%
P1 = 22_28_4033: alternate symbols: (); part number: 22_28_4033_HDR-3P-22-28-4033
P2-P5 = 2211S_02G: alternate symbols: (); part number: 2211S_02G_HDR-2P-2211S-02G
P6 = PJ_002AH: alternate symbols: (); part number: PJ_002AH_POWER_JACK-PJ-002AH
Q1 Q2 = BSS123: alternate symbols: (); part number: BSS123_SOT-23-3-BSS123
R1-R10 R17-R33 R35 R36 R48-R67 R69-R72 R75 R76 R94 R102 R104-R106 R108 R109 R111 R135 R136 R144 R146 R162-R169 R180-R182 R185 R186 R188 = RESISTOR: alternate symbols: (); part number: RESISTOR_0201-CRCW02010000Z0ED,0,JUMPER
R11 R12 R37 R78 R97 R107 R119 R120 R128 R129 R141 R152 R159 R177 R183 R187 = RESISTOR: alternate symbols: (); part number: RESISTOR_0402-ERJ-2GE0R00,0,JUMPER
R13 R15 R16 R41 R43 R46 R47 R73 R74 R81 R83 R84 R86 R89 R91 R98 R113 R145 R148 R155 R170 R171 R178 R179 R184 = RESISTOR: alternate symbols: (); part number: RESISTOR_0402-CRCW040210K0FK,10K,1%
R14 R110 R138 R158 R172 R173 = RESISTOR: alternate symbols: (); part number: RESISTOR_0402-CRCW0402100KFK,100K,1%
R34 R115 R118 = RESISTOR: alternate symbols: (); part number: RESISTOR_2010-CRCW20100000Z0,0.00,1%
R38 = RESISTOR: alternate symbols: (); part number: RESISTOR_0402-CRCW040247K5FK,47.5K,1%
R39 R40 R42 R44 R45 = RESISTOR: alternate symbols: (); part number: RESISTOR_0201-CRCW020133R2FN,33.2,1%
R68 R77 R79 R80 R154 = RESISTOR: alternate symbols: (); part number: RESISTOR_0402-ERJ-2GEJ101,100,5%
R82 = RESISTOR: alternate symbols: (); part number: RESISTOR_0402-CRCW040212K7FK,12.7K,1%
R85 R87 = RESISTOR: alternate symbols: (); part number: RESISTOR_0402-CRCW040261R9FK,61.9,1%
R88 R96 R114 = RESISTOR: alternate symbols: (); part number: RESISTOR_0402-CRCW040282K5FK,82.5K,1%
R90 = RESISTOR: alternate symbols: (); part number: RESISTOR_0402-ERJ-2GEJ361,360,5%
R92 R95 R99 = RESISTOR: alternate symbols: (); part number: RESISTOR_0402-CRCW04027K87FK,7.87K,1%
R93 R101 R112 = RESISTOR: alternate symbols: (); part number: RESISTOR_0402-CRCW0402750RFK,750,1%
R100 R103 R116 R117 R160 = RESISTOR: alternate symbols: (); part number: RESISTOR_0402-ERJ-2GEJ511,510,5%
R121 R132 = RESISTOR: alternate symbols: (); part number: RESISTOR_0402-CRCW04022K80FK,2.8K,1%
R122 R131 R139 = RESISTOR: alternate symbols: (); part number: RESISTOR_0402-CRCW04021K96FK,1.96K,1%
R123 R124 R126 R127 R140 = RESISTOR: alternate symbols: (); part number: RESISTOR_0402-CRCW04021K00FK,1K,1%
R125 = RESISTOR: alternate symbols: (); part number: RESISTOR_0402-CRCW04024K87FK,4.87K,1%
R130 R133 R137 R161 R175 R176 R189 = RESISTOR: alternate symbols: (); part number: RESISTOR_0603-MCT06030Z0000ZP500,0,JUMPER
R134 = RESISTOR: alternate symbols: (); part number: RESISTOR_0402-CRCW040249R9FK,49.9,1%
R142 R150 = RESISTOR: alternate symbols: (); part number: RESISTOR_0402-ERJ-2RKF4991X,4.99K,1%
R143 R147 = RESISTOR: alternate symbols: (); part number: RESISTOR_0402-CRCW04024K99FK,4.99K,1%
R149 = RESISTOR: alternate symbols: (); part number: RESISTOR_0402-ERJ-2GEJ102,1K,5%
R151 R153 = RESISTOR: alternate symbols: (); part number: RESISTOR_0402-CRCW0402330KFK,330K,1%
R156 = RESISTOR: alternate symbols: (); part number: RESISTOR_0402-CRCW040249K9FK,49.9K,1%
R157 R174 = RESISTOR: alternate symbols: (); part number: RESISTOR_0402-CRCW040230K0FK,30K,1%
R190-R193 = RESISTOR: alternate symbols: (); part number: RESISTOR_0402-CRCW04023R83FK,3.83,1%
SW1 SW2 = KMR2XXG: alternate symbols: (); part number: KMR2XXG_SW-4P-KMR243GLFG
TP1 TP2 = TP: alternate symbols: (); part number: TP_TP-040PTH
U1 = S25FL116K0XNFV010: alternate symbols: (); part number: S25FL116K0XNFV010_SON-8-S25FL116K0XNFV010
U2 = AR1243_PRELIMINARY: alternate symbols: (); part number: AR1243_PRELIMINARY_BGA-161-FULL-AR1243_PRELIMINARY
U3 = SN65HVDA540QD: alternate symbols: (); part number: SN65HVDA540QD_SOIC-8-SN65HVDA540QD
U4 = TPS7A8101: alternate symbols: (); part number: TPS7A8101_SON-8-TPS7A8101QDRBRQ1
U5 = TPS7A8801: alternate symbols: (); part number: TPS7A8801_QFN-20-TPS7A8801RTJ
U6 = TM4C1294NCPDTT3: alternate symbols: (); part number: TM4C1294NCPDTT3_QFP-128-QUAD-TM4C1294NCPDTT3
U7 = LM4040C25Q: alternate symbols: (); part number: LM4040C25Q_SOT-23-3-LM4040C25QDBZ
U8 = P87524BRNFRQ1_ES2_2_PRELIMINARY: alternate symbols: (); part number: P87524BRNFRQ1_ES2_2_PRELIMINARY_VQFN-26-P87524BRNFRQ1_ES2.2_PRELIMINARY
U9 = TPS79601DRB: alternate symbols: (); part number: TPS79601DRB_SON-8-TPS79601DRB
U10 = TPD4E004DRY: alternate symbols: (); part number: TPD4E004DRY_SON-6P-TPD4E004DRY
U11 U12 = TMP112AIDRL: alternate symbols: (); part number: TMP112AIDRL_SOTFL-6-TMP112AIDRL
Y1 = CX3225SA: alternate symbols: (); part number: CX3225SA_XTAL-4P-CX3225SA40000D0PTWCC,40MHZ
Y2 = NX3225SA: alternate symbols: (); part number: NX3225SA_XTAL-4P-NX3225SA-16.000M-STD-CRS-2,16MHZ

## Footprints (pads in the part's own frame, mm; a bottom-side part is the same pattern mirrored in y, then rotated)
BGA161C65P15X15_1040X1040X120
  round 0.33 smd: A1(-4.55,4.55) A2(-3.9,4.55) A3(-3.25,4.55) A5(-1.95,4.55) A7(-0.65,4.55) A9(0.65,4.55) A10(1.3,4.55) A13(3.25,4.55) A14(3.9,4.55) A15(4.55,4.55) B1(-4.55,3.9) B2(-3.9,3.9) B3(-3.25,3.9) B4(-2.6,3.9) B5(-1.95,3.9) B6(-1.3,3.9) B7(-0.65,3.9) B8(0,3.9) B9(0.65,3.9) B10(1.3,3.9) B11(1.95,3.9) B12(2.6,3.9) B13(3.25,3.9) B14(3.9,3.9) B15(4.55,3.9) C1(-4.55,3.25) C2(-3.9,3.25) C3(-3.25,3.25) C4(-2.6,3.25) C5(-1.95,3.25) C6(-1.3,3.25) C7(-0.65,3.25) C8(0,3.25) C9(0.65,3.25) C13(3.25,3.25) C14(3.9,3.25) C15(4.55,3.25) D1(-4.55,2.6) D2(-3.9,2.6) D13(3.25,2.6) D15(4.55,2.6) E1(-4.55,1.95) E2(-3.9,1.95) E3(-3.25,1.95) E5(-1.95,1.95) E6(-1.3,1.95) E8(0,1.95) E10(1.3,1.95) E11(1.95,1.95) E13(3.25,1.95) E14(3.9,1.95) E15(4.55,1.95) F2(-3.9,1.3) F3(-3.25,1.3) F5(-1.95,1.3) F9(0.65,1.3) F11(1.95,1.3) F13(3.25,1.3) F14(3.9,1.3) G1(-4.55,0.65) G2(-3.9,0.65) G3(-3.25,0.65) G5(-1.95,0.65) G6(-1.3,0.65) G7(-0.65,0.65) G8(0,0.65) G10(1.3,0.65) G13(3.25,0.65) G14(3.9,0.65) G15(4.55,0.65) H2(-3.9,0) H3(-3.25,0) H5(-1.95,0) H7(-0.65,0) H9(0.65,0) H11(1.95,0) H13(3.25,0) H14(3.9,0) H15(4.55,0) J1(-4.55,-0.65) J2(-3.9,-0.65) J3(-3.25,-0.65) J5(-1.95,-0.65) J6(-1.3,-0.65) J7(-0.65,-0.65) J8(0,-0.65) J10(1.3,-0.65) J13(3.25,-0.65) J14(3.9,-0.65) J15(4.55,-0.65) K2(-3.9,-1.3) K3(-3.25,-1.3) K5(-1.95,-1.3) K7(-0.65,-1.3) K8(0,-1.3) K9(0.65,-1.3) K10(1.3,-1.3) K11(1.95,-1.3) K13(3.25,-1.3) K14(3.9,-1.3) K15(4.55,-1.3) L1(-4.55,-1.95) L2(-3.9,-1.95) L3(-3.25,-1.95) L5(-1.95,-1.95) L6(-1.3,-1.95) L8(0,-1.95) L10(1.3,-1.95) L13(3.25,-1.95) L14(3.9,-1.95) L15(4.55,-1.95) M2(-3.9,-2.6) M3(-3.25,-2.6) M13(3.25,-2.6) M14(3.9,-2.6) M15(4.55,-2.6) N1(-4.55,-3.25) N2(-3.9,-3.25) N3(-3.25,-3.25) N4(-2.6,-3.25) N5(-1.95,-3.25) N6(-1.3,-3.25) N7(-0.65,-3.25) N8(0,-3.25) N9(0.65,-3.25) N10(1.3,-3.25) N11(1.95,-3.25) N12(2.6,-3.25) N13(3.25,-3.25) N14(3.9,-3.25) N15(4.55,-3.25) P1(-4.55,-3.9) P2(-3.9,-3.9) P3(-3.25,-3.9) P4(-2.6,-3.9) P5(-1.95,-3.9) P6(-1.3,-3.9) P7(-0.65,-3.9) P8(0,-3.9) P9(0.65,-3.9) P10(1.3,-3.9) P11(1.95,-3.9) P12(2.6,-3.9) P13(3.25,-3.9) P14(3.9,-3.9) P15(4.55,-3.9) R1(-4.55,-4.55) R2(-3.9,-4.55) R3(-3.25,-4.55) R4(-2.6,-4.55) R5(-1.95,-4.55) R6(-1.3,-4.55) R7(-0.65,-4.55) R8(0,-4.55) R9(0.65,-4.55) R10(1.3,-4.55) R11(1.95,-4.55) R12(2.6,-4.55) R13(3.25,-4.55) R14(3.9,-4.55) R15(4.55,-4.55)
CAPMP3528X210N
  rect 1.8x2.25 smd: 1(-1.45,0) 2(1.45,0)
CC0201
  rect 0.46x0.419 smd: 1(-0.33,0) 2(0.33,0)
CC0402
  rect 0.579x0.66 smd: 1(-0.49,0) 2(0.49,0)
CC0603
  rect 0.95x1.001 smd: 1(-0.8,0) 2(0.8,0)
CC0805
  rect 1.151x1.45 smd: 1(-0.899,0) 2(0.899,0)
CC1206
  rect 1.151x1.801 smd: 1(-1.501,0) 2(1.501,0)
CINCH_128-0711-201
  rect 2.2x1.05 smd: G1(0,1.475) G2(0,-1.475)
  rect 1.05x1 smd: S(1.525,0)
CUI_PJ-002AH
  rect 4x1.5 hole 3.5x1: 1(0,0)
  rect 3.5x1.5 hole 3x1: 2(0,-6)
  rect 1.5x3.5 hole 1x3: 3(4.7,-3)
DFN100X60X50-2N
  rect 0.35x0.62 smd: A(0.34,0) C(-0.34,0)
DIOM5436X295N
  rect 2.15x2.2 smd: A(2.3,0) C(-2.3,0)
FB0805
  rect 1.199x1.45 smd: 1(-0.85,0) 2(0.85,0)
FUSE1206
  rect 1.14x2.029 smd: 1(-1.335,0) 2(1.335,0)
INDC2520X120N
  rect 0.8x2 smd: 1(-1,0) 2(1,0)
LED0603
  rect 0.899x0.95 smd: A(0.8,0) C(-0.8,0)
MOLEX_22-28-4033
  rect 1.519x1.519 hole 1.021: 1(0,0)
  round 1.519 hole 1.021: 2(0,-2.54) 3(0,-5.08)
MOLEX_105017-0001
  rect 1.5x1.9 smd: (-1,-0.15) (1,-0.15)
  rect 0.4x1.35 smd: 1(-1.3,2.55) 2(-0.65,2.55) 3(0,2.55) 4(0.65,2.55) 5(1.3,2.55)
  round 1.45 hole 0.85: G1(-2.5,2.55) G2(2.5,2.55)
  oval 1.1x1.8 hole 0.6x1.3: G3(-3.5,-0.15) G4(3.5,-0.15)
MULTICOMP_2211S-02G
  rect 1.6x1.6 hole 1.1: 1(0,0)
  round 1.6 hole 1.1: 2(2.54,0)
OST_OSTTE030161
  rect 1.702x1.702 hole 1.202: 1(0,0)
  round 1.702 hole 1.202: 2(3.5,0) 3(7,0)
P87524BRNFRQ1_ES2_2_PRELIMINARY
  custom 0.195x0.195 smd: 1(-1.595,1.82) 8(-1.595,-1.82) 14(1.595,-1.82) 21(1.595,1.82)
  rect 0.6x0.25 smd: 2(-1.9,1.25) 3(-1.9,0.75) 4(-1.9,0.25) 5(-1.9,-0.25) 6(-1.9,-0.75) 7(-1.9,-1.25) 15(1.9,-1.25) 16(1.9,-0.75) 17(1.9,-0.25) 18(1.9,0.25) 19(1.9,0.75) 20(1.9,1.25)
  rect 0.25x1.82 smd: 9(-1,-1.54) 10(-0.5,-1.54) 11(0,-1.54) 12(0.5,-1.54) 13(1,-1.54) 22(1,1.54) 23(0.5,1.54) 24(0,1.54) 25(-0.5,1.54) 26(-1,1.54)
  rect 2.24x0.66 smd: EP(0,0)
PSON50P100X145X60-6N
  rect 0.399x0.3 smd: 1(-0.3,0.5) 2(-0.3,0) 3(-0.3,-0.5) 4(0.3,-0.5) 5(0.3,0) 6(0.3,0.5)
QFN50P400X400X80_EPE-21N
  rect 0.851x0.3 smd: 1(-2,1) 2(-2,0.5) 3(-2,0) 4(-2,-0.5) 5(-2,-1) 11(2,-1) 12(2,-0.5) 13(2,0) 14(2,0.5) 15(2,1)
  rect 0.3x0.851 smd: 6(-1,-2) 7(-0.5,-2) 8(0,-2) 9(0.5,-2) 10(1,-2) 16(1,2) 17(0.5,2) 18(0,2) 19(-0.5,2) 20(-1,2)
  rect 2.8x2.8 smd: EP(0,0)
QFP40P1600X1600X120-128N
  rect 1.45x0.201 smd: 1(-7.7,6.2) 2(-7.7,5.8) 3(-7.7,5.4) 4(-7.7,5) 5(-7.7,4.6) 6(-7.7,4.2) 7(-7.7,3.8) 8(-7.7,3.4) 9(-7.7,3) 10(-7.7,2.6) 11(-7.7,2.2) 12(-7.7,1.8) 13(-7.7,1.4) 14(-7.7,1) 15(-7.7,0.6) 16(-7.7,0.2) 17(-7.7,-0.2) 18(-7.7,-0.6) 19(-7.7,-1) 20(-7.7,-1.4) 21(-7.7,-1.8) 22(-7.7,-2.2) 23(-7.7,-2.6) 24(-7.7,-3) 25(-7.7,-3.4) 26(-7.7,-3.8) 27(-7.7,-4.2) 28(-7.7,-4.6) 29(-7.7,-5) 30(-7.7,-5.4) 31(-7.7,-5.8) 32(-7.7,-6.2) 65(7.7,-6.2) 66(7.7,-5.8) 67(7.7,-5.4) 68(7.7,-5) 69(7.7,-4.6) 70(7.7,-4.2) 71(7.7,-3.8) 72(7.7,-3.4) 73(7.7,-3) 74(7.7,-2.6) 75(7.7,-2.2) 76(7.7,-1.8) 77(7.7,-1.4) 78(7.7,-1) 79(7.7,-0.6) 80(7.7,-0.2) 81(7.7,0.2) 82(7.7,0.6) 83(7.7,1) 84(7.7,1.4) 85(7.7,1.8) 86(7.7,2.2) 87(7.7,2.6) 88(7.7,3) 89(7.7,3.4) 90(7.7,3.8) 91(7.7,4.2) 92(7.7,4.6) 93(7.7,5) 94(7.7,5.4) 95(7.7,5.8) 96(7.7,6.2)
  rect 0.201x1.45 smd: 33(-6.2,-7.7) 34(-5.8,-7.7) 35(-5.4,-7.7) 36(-5,-7.7) 37(-4.6,-7.7) 38(-4.2,-7.7) 39(-3.8,-7.7) 40(-3.4,-7.7) 41(-3,-7.7) 42(-2.6,-7.7) 43(-2.2,-7.7) 44(-1.8,-7.7) 45(-1.4,-7.7) 46(-1,-7.7) 47(-0.6,-7.7) 48(-0.2,-7.7) 49(0.2,-7.7) 50(0.6,-7.7) 51(1,-7.7) 52(1.4,-7.7) 53(1.8,-7.7) 54(2.2,-7.7) 55(2.6,-7.7) 56(3,-7.7) 57(3.4,-7.7) 58(3.8,-7.7) 59(4.2,-7.7) 60(4.6,-7.7) 61(5,-7.7) 62(5.4,-7.7) 63(5.8,-7.7) 64(6.2,-7.7) 97(6.2,7.7) 98(5.8,7.7) 99(5.4,7.7) 100(5,7.7) 101(4.6,7.7) 102(4.2,7.7) 103(3.8,7.7) 104(3.4,7.7) 105(3,7.7) 106(2.6,7.7) 107(2.2,7.7) 108(1.8,7.7) 109(1.4,7.7) 110(1,7.7) 111(0.6,7.7) 112(0.2,7.7) 113(-0.2,7.7) 114(-0.6,7.7) 115(-1,7.7) 116(-1.4,7.7) 117(-1.8,7.7) 118(-2.2,7.7) 119(-2.6,7.7) 120(-3,7.7) 121(-3.4,7.7) 122(-3.8,7.7) 123(-4.2,7.7) 124(-4.6,7.7) 125(-5,7.7) 126(-5.4,7.7) 127(-5.8,7.7) 128(-6.2,7.7)
RC0201
  rect 0.46x0.419 smd: 1(-0.33,0) 2(0.33,0)
RC0402
  rect 0.569x0.62 smd: 1(-0.48,0) 2(0.48,0)
RC0402_40
  rect 0.569x0.62 smd: 1(-0.48,0) 2(0.48,0)
RC0603
  rect 0.899x1.001 smd: 1(-0.8,0) 2(0.8,0)
RC2010
  rect 1.151x2.7 smd: 1(-2.45,0) 2(2.45,0)
SAMTEC_QSH-030-01-X-D-A
  round 0.249 hole 1.021 unplated: (-10.065,2.67) (10.065,2.67)
  rect 0.28x2.27 smd: 1(-7.25,-2.87) 2(-7.25,2.87) 3(-6.75,-2.87) 4(-6.75,2.87) 5(-6.25,-2.87) 6(-6.25,2.87) 7(-5.75,-2.87) 8(-5.75,2.87) 9(-5.25,-2.87) 10(-5.25,2.87) 11(-4.75,-2.87) 12(-4.75,2.87) 13(-4.25,-2.87) 14(-4.25,2.87) 15(-3.75,-2.87) 16(-3.75,2.87) 17(-3.25,-2.87) 18(-3.25,2.87) 19(-2.75,-2.87) 20(-2.75,2.87) 21(-2.25,-2.87) 22(-2.25,2.87) 23(-1.75,-2.87) 24(-1.75,2.87) 25(-1.25,-2.87) 26(-1.25,2.87) 27(-0.75,-2.87) 28(-0.75,2.87) 29(-0.25,-2.87) 30(-0.25,2.87) 31(0.25,-2.87) 32(0.25,2.87) 33(0.75,-2.87) 34(0.75,2.87) 35(1.25,-2.87) 36(1.25,2.87) 37(1.75,-2.87) 38(1.75,2.87) 39(2.25,-2.87) 40(2.25,2.87) 41(2.75,-2.87) 42(2.75,2.87) 43(3.25,-2.87) 44(3.25,2.87) 45(3.75,-2.87) 46(3.75,2.87) 47(4.25,-2.87) 48(4.25,2.87) 49(4.75,-2.87) 50(4.75,2.87) 51(5.25,-2.87) 52(5.25,2.87) 53(5.75,-2.87) 54(5.75,2.87) 55(6.25,-2.87) 56(6.25,2.87) 57(6.75,-2.87) 58(6.75,2.87) 59(7.25,-2.87) 60(7.25,2.87)
  rect 2.54x0.43 smd: G1(-8.07,0) G4(8.06,0)
  rect 4.7x0.43 smd: G2(-3.18,0) G3(3.17,0)
SAMTEC_SSM-103-XX-SV
  rect 1.02x1.905 smd: 1(-2.54,-1.777) 2(0,1.777) 3(2.54,-1.777)
SAMTEC_SSM-110-XX-DV
  rect 1.02x2.22 smd: 1(11.43,-2.825) 2(11.43,2.825) 3(8.89,-2.825) 4(8.89,2.825) 5(6.35,-2.825) 6(6.35,2.825) 7(3.81,-2.825) 8(3.81,2.825) 9(1.27,-2.825) 10(1.27,2.825) 11(-1.27,-2.825) 12(-1.27,2.825) 13(-3.81,-2.825) 14(-3.81,2.825) 15(-6.35,-2.825) 16(-6.35,2.825) 17(-8.89,-2.825) 18(-8.89,2.825) 19(-11.43,-2.825) 20(-11.43,2.825)
SOIC127P600X175-8N
  rect 1.549x0.599 smd: 1(-2.65,1.905) 2(-2.65,0.635) 3(-2.65,-0.635) 4(-2.65,-1.905) 5(2.65,-1.905) 6(2.65,-0.635) 7(2.65,0.635) 8(2.65,1.905)
SON65P300X300X100-9
  custom 0.088x0.088 smd: 1(-1.475,0.975) 2(-1.475,0.325) 3(-1.475,-0.325) 4(-1.475,-0.975) 5(1.475,-0.975) 6(1.475,-0.325) 7(1.475,0.325) 8(1.475,0.975)
  custom 0.375x0.375 smd: EP(0,0)
SON65P300X300X100_EPA-9N
  rect 0.851x0.351 smd: 1(-1.5,0.975) 2(-1.5,0.325) 3(-1.5,-0.325) 4(-1.5,-0.975) 5(1.5,-0.975) 6(1.5,-0.325) 7(1.5,0.325) 8(1.5,0.975)
  rect 1.75x2.499 smd: EP(0,0)
SON127P600X500X80_EPA-9N
  rect 1.049x0.45 smd: 1(-2.85,1.905) 2(-2.85,0.635) 3(-2.85,-0.635) 4(-2.85,-1.905) 5(2.85,-1.905) 6(2.85,-0.635) 7(2.85,0.635) 8(2.85,1.905)
  rect 3.5x4.1 smd: EP(0,0)
SOT95P237X112-3N
  rect 1.049x0.65 smd: 1(-1.15,0.95) 2(-1.15,-0.95) 3(1.15,0)
SOT95P240X120-3N
  rect 1.05x0.7 smd: 1(-1.15,0.95) 2(-1.15,-0.95) 3(1.15,0)
SOTFL50P160X60-6N
  rect 0.671x0.3 smd: 1(-0.74,0.5) 2(-0.74,0) 3(-0.74,-0.5) 4(0.74,-0.5) 5(0.74,0) 6(0.74,0.5)
SW_KMR2XXG
  rect 0.899x1.001 smd: 1(-2.05,0.8) 2(2.05,0.8) 3(-2.05,-0.8) 4(2.05,-0.8)
  rect 1.7x0.55 smd: G(0,1.425)
TP_C163H102
  round 1.626 hole 1.02: 1(0,0)
unnamed#2
  round 7 hole 4: 1(0,0)
unnamed#3
  round 4.064 hole 4.064 unplated: (0,0)
XTAL_CX3225SA
  rect 1.45x1.049 smd: 1(-1.075,-0.925) 2(1.075,-0.925) 3(1.075,0.925) 4(-1.075,0.925)
XTAL_NX3225SA
  rect 1.4x1.199 smd: 1(-1.1,-0.8) 2(1.1,-0.8) 3(1.1,0.8) 4(-1.1,0.8)

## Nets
3V3_BRD: C41.2 C42.2 C43.2 C50.2 C61.2 C76.2 C77.2 C78.2 R124.2 R127.2 R134.2 R140.2 R155.2 R156.2 R179.2 R183.2 R184.2 R187.2 R188.2 U6.7(VDD1) U6.8(VDDA) U6.16(VDD2) U6.26(VDD3) U6.28(VDD4) U6.39(VDD5) U6.47(VDD6) U6.51(VDD7) U6.52(VDD8) U6.69(VDD9) U6.79(VDD10) U6.90(VDD11) U6.101(VDD12) U6.113(VDD13) U6.122(VDD14) U9.3(OUT1) U9.4(OUT2)
3V3_MON_XDS_1: R158.2 R159.2 U9.8(EN)
5V_IN: FB1.2 FB2.2 P5.1 R34.2 R78.2 R100.2 R103.2 R115.2 R117.2 R118.1 R149.2 R176.2
5V_UNREG: C59.2 C60.2 C68.2 C72.2 C73.2 P5.2 R118.2 U8.9(VIN_B0) U8.13(VIN_B1) U8.18(VANA) U8.22(VIN_B3) U8.26(VIN_B2)
+3.3VD: C5.2 C20.2 P2.2 P3.2 P4.2 R14.2 R15.2 R16.2 R37.2 R38.2 R41.2 R43.2 R68.2 R74.2 R90.2 R91.2 R130.2 R133.2 R170.2 R171.2 R172.2 R173.2 R178.1 U2.R13(VIOIN) U3.5(VIO)
GND: C1.1 C2.1 C3.1 C4.1 C5.1 C6.1 C7.1 C8.1 C9.1 C10.1 C11.1 C12.1 C13.1 C14.1 C15.1 C16.1 C17.1 C19.1 C20.1 C21.1 C22.1 C23.1 C24.1 C25.1 C26.2 C27.2 C29.1 C30.1 C31.1 C32.1 C33.1 C34.1 C35.1 C36.1 C37.1 C38.1 C39.1 C40.1 C41.1 C42.1 C43.1 C44.1 C45.1 C47.1 C48.1 C49.1 C50.1 C51.1 C52.1 C53.1 C54.1 C55.1 C56.1 C57.1 C58.1 C59.1 C60.1 C61.1 C62.1 C63.1 C64.1 C65.1 C66.1 C67.1 C68.1 C69.1 C70.1 C71.1 C72.1 C73.1 C74.1 C75.1 C76.1 C77.1 C79.1 C80.1 C81.1 C82.1 C83.1 C84.1 C85.1 C86.1 C87.1 C88.1 C89.1 D3.A DS2.C J1.18 J1.24 J1.30 J1.36 J1.42 J1.48 J1.54 J1.60 J1.G1 J1.G2 J1.G3 J1.G4 J2.G1 J2.G2 J3.2 J4.1 J4.2 J5.2 J6.4 J7.1 J7.2 P1.2 P6.2 P6.3 Q1.2(S) Q2.2(S) R13.1 R47.2 R73.1 R79.1 R81.1 R83.2 R86.2 R88.1 R96.1 R110.1 R114.1 R119.1 R121.1 R123.2 R125.1 R126.2 R132.1 R138.1 R139.1 R153.1 R157.1 R158.1 R174.1 R175.1 R181.1 SW1.G(GND) SW2.G(GND) TP1.1 U1.4(VSS) U1.EP U2.A1(VSSA1) U2.A3(VSSA2) U2.A5(VSSA3) U2.A7(VSSA4) U2.A9(VSSA5) U2.A15(VSSA6) U2.B1(FM_CW_SYNCIN1) U2.B3(VSSA7) U2.B5(VSSA8) U2.B7(VSSA9) U2.B9(VSSA10) U2.B13(VSSA43) U2.B14(VSSA11) U2.C1(VSSA12) U2.C3(VSSA13) U2.C4(VSSA14) U2.C5(VSSA15) U2.C6(VSSA16) U2.C7(VSSA17) U2.C8(VSSA18) U2.C9(VSSA19) U2.C15(VSSA20) U2.E1(VSSA21) U2.E2(VSSA22) U2.E3(VSSA23) U2.E5(VSS19) U2.E6(VSS1) U2.E8(VSS2) U2.E10(VSS3) U2.E11(VSS4) U2.E13(VSSA24) U2.E15(VSSA25) U2.F3(VSSA26) U2.F9(VSS6) U2.F11(VSS7) U2.G1(VSSA27) U2.G2(VSSA28) U2.G3(VSSA29) U2.G6(VSS8) U2.G7(VSS5) U2.G8(VSS9) U2.G10(VSS10) U2.H3(VSSA30) U2.H7(VSS11) U2.H9(VSS12) U2.H11(VSS14) U2.J1(VSSA31) U2.J2(VSSA32) U2.J3(VSSA33) U2.J6(VSS16) U2.J7(VSS13) U2.J8(VSS17) U2.J10(VSS18) U2.K3(VSSA34) U2.K7(VSS20) U2.K8(VSS21) U2.K9(VSS22) U2.K10(VSS23) U2.K11(VSS24) U2.L1(VSSA35) U2.L2(VSSA36) U2.L3(VSSA37) U2.L5(VSS25) U2.L6(VSS26) U2.L8(VSS27) U2.L10(VSS28) U2.M3(VSSA38) U2.N1(VSSA39) U2.N2(VSSA40) U2.N3(VSSA41) U2.R1(VSSA42) U2.R15(VSS29) U3.2(GND) U4.4(GND) U4.EP(EPAD) U5.3(GND1) U5.13(GND2) U5.EP(GND3) U6.10(GNDA) U6.17(GND1) U6.48(GND2) U6.55(GND3) U6.58(GND4) U6.64(WAKE*) U6.66(XOSC0) U6.80(GND5) U6.114(GND6) U7.2(A) U8.4(AGND1) U8.11(PGND_B01) U8.17(AGND2) U8.24(PGND_B23) U8.EP(AGND3) U9.6(GND) U9.EP(EPAD) U10.3(GND) U11.2(GND) U12.2(GND) Y1.2(THDCON<0>) Y1.4(THDCON<0>) Y2.2(THDCON<0>) Y2.4(THDCON<0>)
VBUS_1_DETECT: C69.2 R151.2 R153.2 U6.1(PD0)
VDDC_1: C62.2 C64.2 C74.2 C75.2 U6.87(VDDC1) U6.115(VDDC2)
AR_1P3_RF1: C36.2 C37.2 C38.2 C45.2 C46.2 C47.2 R131.2 R189.2 U2.G5(VIN_13RF1_1) U2.H5(VIN_13RF1_2) U2.J5(VIN_13RF1_3) U5.14(OUT1_1) U5.15(OUT1_2)
AR_1P3_RF2: C28.2 C33.2 C34.2 C35.2 C57.2 C58.2 L5.2 R122.2 R137.1 R189.1 U2.C2(VIN_13RF2_1) U2.D2(VIN_13RF2_2) U5.11(OUT2_1) U5.12(OUT2_2)
AR_1V4_APLL: C13.2 U2.A10(VOUT_14APLL)
AR_1V4_SYNTH: C14.2 U2.A13(VOUT_14SYNTH)
AR_1V8: C12.2 C17.2 C18.2 C19.2 C39.2 C48.2 C51.2 C52.2 C53.2 L6.2 R82.2 U2.B11(VIN_18CLK) U2.B12(VIN_18VCO) U2.D13(VIOIN_18DIFF) U2.F5(VIN_18BB_2) U2.K5(VIN_18BB_1) U2.K13(VIOIN_18) U4.1(OUT1) U4.2(OUT2)
AR_ANAMUX: P1.3 U2.C13(ANAMUX)
AR_ANATEST1: R104.2 U2.P1(ANALOGTEST1)
AR_ANATEST2: R94.2 U2.P2(ANALOGTEST2)
AR_ANATEST3: R105.2 U2.P3(ANALOGTEST3)
AR_ANATEST4: R106.2 U2.R2(ANALOGTEST4)
AR_BSS_LOGGER: R31.1 R135.1 U2.R4(RES3)
AR_CS1: R1.2 R14.1 R17.1 U2.R7(SPI_CS_1)
AR_GPIO_0: R164.1 R177.2 U2.N4(GPIO_0)
AR_GPIO_1: R9.2 R72.2 U2.N7(GPIO_1)
AR_GPIO_2: R8.2 R110.2 R116.1 U2.N13(GPIO_2)
AR_HOSTINTR1: R10.2 R13.2 R64.2 U2.P6(SPI_HOST_INTR_1)
AR_LVDS_VALIDM: R60.2 U2.N14(HS_DEBUG2_M)
AR_LVDS_VALIDP: R61.2 U2.N15(HS_DEBUG2_P)
AR_LVDSCSI_0M: R48.2 U2.G14(CSI2_TXM_0)
AR_LVDSCSI_0P: R49.2 U2.G15(CSI2_TXP_0)
AR_LVDSCSI_1M: R50.2 U2.H14(CSI2_TXM_1)
AR_LVDSCSI_1P: R51.2 U2.H15(CSI2_TXP_1)
AR_LVDSCSI_2M: R54.2 U2.K14(CSI2_TXM_2)
AR_LVDSCSI_2P: R55.2 U2.K15(CSI2_TXP_2)
AR_LVDSCSI_3M: R56.2 U2.L14(CSI2_TXM_3)
AR_LVDSCSI_3P: R57.2 U2.L15(CSI2_TXP_3)
AR_LVDSCSI_CLKM: R52.2 U2.J14(CSI2_CLKM)
AR_LVDSCSI_CLKP: R53.2 U2.J15(CSI2_CLKP)
AR_LVDSCSI_FRCLKM: R58.2 U2.M14(HS_DEBUG1_M)
AR_LVDSCSI_FRCLKP: R59.2 U2.M15(HS_DEBUG1_P)
AR_MCUCLKOUT: R25.1 U2.N9(MCU_CLKOUT)
AR_MISO1: R5.2 R6.2 R7.2 R11.1 U2.P5(MISO_1)
AR_MOSI1: R3.2 R4.2 R12.1 R28.1 U2.R8(MOSI_1)
AR_MSS_LOGGER: R26.1 R136.1 U2.R5(RES4)
AR_NERR_OUT: DS1.C R19.1 R63.2 R91.1 U2.N8(NERROR_OUT)
AR_NERRIN: R16.1 R24.1 U2.P7(NERROR_IN)
AR_NRST: C11.2 D1.A D2.A R74.1 R160.1 SW2.4 U2.P12(NRESET)
AR_NRST_MCU: R2.2 R20.1 R77.1
AR_NRST_XDS: R80.1 U6.40(PA6)
AR_OSC_CLKOUT: R111.1 U2.A14(OSC_CLKOUT)
AR_PMIC_CLKOUT_SOP2: R97.1 R98.1 R109.2 U2.P13(PMIC_CLKOUT)
AR_QSPI_CS: R38.1 U1.1(CS*) U2.P8(QSPI_CS)
AR_QSPI_D0: R45.2 U2.R11(QSPI_0)
AR_QSPI_D1: R39.1 U2.P9(QSPI_1)
AR_QSPI_D2: R42.1 R43.1 U2.R12(QSPI_2)
AR_QSPI_D3: R40.2 R41.1 U2.P10(QSPI_3)
AR_QSPI_SCLK: R44.2 U2.R10(QSPI_CLK)
AR_RS232RX: R33.1 R129.1 R166.1 R168.1 R172.1 U2.N5(RS232_RX)
AR_RS232TX: R21.1 R128.1 R167.1 R169.1 R173.1 U2.N6(RS232_TX)
AR_SCL: R22.1 R146.1 R163.1 R171.1 R180.1 R185.1 U2.P4(RES1)
AR_SDA: R23.1 R144.1 R162.1 R170.1 R182.2 R186.2 U2.R3(RES2)
AR_SPICLK1: R75.1 R76.1 U2.R9(SPI_CLK_1)
AR_SYNC_IN: R62.2 R165.1 U2.N10(SYNC_IN)
AR_SYNC_OUT_SOP1: R108.2 R113.1 U2.P11(SYNC_OUT)
AR_TCK: R66.2 R70.1 U2.M13(TCK)
AR_TDI: R29.1 R30.1 U2.H13(TDI)
AR_TDO_SOP0: R67.2 R71.1 R89.1 U2.J13(TDO)
AR_TMS: R65.2 R69.1 U2.L13(TMS)
AR_VBGAP: C56.2 U2.B10(VBGAP)
AR_VOUT_PA: C10.2 C65.2 C83.2 R137.2 U2.A2(VOUT_PA1) U2.B2(VOUT_PA2)
AR_VSENSE: P1.1 U2.C14(VSENSE)
AR_WARMRST: R15.1 R18.1 U2.N12(WARM_RESET)
AR_XTALM: C9.2 U2.F14(CLKM) Y1.1
AR_XTALP: C15.2 U2.E14(CLKP) Y1.3
CAN1_RX: R12.2 U3.4(RXD)
CAN1_TX: R11.2 U3.1(TXD)
LDO_01_EN: R83.1 R84.2 U4.5(EN)
LDO_02_EN: R46.2 R47.1 U5.6(EN2) U5.20(EN1)
MCU_3V3: J4.3 J6.1 R130.1
MCU_5V: J6.2 J7.3 R115.1
MCU_SOP0: R36.1 R93.2
MCU_SOP1: R35.1 R112.2
MCU_SOP2: R32.1 R101.2
PGOOD: R27.1 R107.2 R138.2 R141.2 R159.1
PMIC_1V2: C3.2 C4.2 C6.2 C7.2 C54.2 L1.2 U2.F13(VDDIN1) U2.N11(VDDIN2) U2.P14(VNWA) U2.P15(VDDIN3) U2.R6(VDDIN4) U2.R14(VIN_SRAM) U8.14(FB_B1)
PMIC_1V8: C30.2 C31.2 C32.2 C40.2 C81.2 L4.1 L5.1 R46.1 R120.2 U5.1(IN1_1) U5.2(IN1_2) U5.4(IN2_1) U5.5(IN2_2) U8.1(FB_B2)
PMIC_2V3: C21.2 C23.2 C25.2 C82.2 L3.2 L6.1 R84.1 U4.7(IN1) U4.8(IN2) U8.21(FB_B3)
PMIC_CLK: R97.2 U8.3(CLKIN)
PMIC_EN: R102.2 R142.1 U8.7(EN1)
PMIC_NRST: R150.2 U8.20(NRST)
PMICOUT_3V3: C55.2 L2.1 R133.1 R141.1 U8.8(FB_B0)
PMICVIO_3V3: R139.2 R142.2 R143.2 R145.2 R147.2 R148.2 R149.1 R150.1
RX1: U2.M2(RX1)
RX2: U2.K2(RX2)
RX3: U2.H2(RX3)
RX4: U2.F2(RX4)
SS_CTRL: R119.2 R120.1 U5.8(SS_CTRL2) U5.18(SS_CTRL1)
SW0: L2.2 R190.2 U8.10(SW_B0)
SW1: L1.1 R191.2 U8.12(SW_B1)
SW2: L4.2 R192.2 U8.25(SW_B2)
SW3: L3.1 R193.2 U8.23(SW_B3)
TX1: U2.B4(TX1)
TX2: U2.B6(TX2)
TX3: U2.B8(TX3)
UNNAMED_2_AR1243PRELIMINARY_I28: C8.2 TP2.1 U2.G13(RES5)
UNNAMED_4_CAPNONPOLARIZED_I52_2: C22.2 U4.6(NR)
UNNAMED_4_CAPNONPOLARIZED_I53_1: C18.1 R81.2 R82.1 U4.3(FB/SNS)
UNNAMED_6_1280711201_I42_S: J2.S R111.2
UNNAMED_6_QSH03001XD_I1_1: J1.1 J1.2 J1.3 R34.1
UNNAMED_6_QSH03001XD_I1_4: J1.4 R67.1
UNNAMED_6_QSH03001XD_I1_5: J1.5 R29.2
UNNAMED_6_QSH03001XD_I1_6: J1.6 R66.1
UNNAMED_6_QSH03001XD_I1_7: J1.7 R17.2
UNNAMED_6_QSH03001XD_I1_8: J1.8 R65.1
UNNAMED_6_QSH03001XD_I1_9: J1.9 R75.2
UNNAMED_6_QSH03001XD_I1_10: J1.10 R64.1
UNNAMED_6_QSH03001XD_I1_11: J1.11 R28.2
UNNAMED_6_QSH03001XD_I1_12: J1.12 R7.1
UNNAMED_6_QSH03001XD_I1_13: J1.13 R27.2
UNNAMED_6_QSH03001XD_I1_14: J1.14 R63.1
UNNAMED_6_QSH03001XD_I1_16: J1.16 R62.1
UNNAMED_6_QSH03001XD_I1_20: J1.20 R61.1
UNNAMED_6_QSH03001XD_I1_22: J1.22 R60.1
UNNAMED_6_QSH03001XD_I1_26: J1.26 R59.1
UNNAMED_6_QSH03001XD_I1_28: J1.28 R58.1
UNNAMED_6_QSH03001XD_I1_32: J1.32 R57.1
UNNAMED_6_QSH03001XD_I1_34: J1.34 R56.1
UNNAMED_6_QSH03001XD_I1_38: J1.38 R55.1
UNNAMED_6_QSH03001XD_I1_40: J1.40 R54.1
UNNAMED_6_QSH03001XD_I1_44: J1.44 R53.1
UNNAMED_6_QSH03001XD_I1_46: J1.46 R52.1
UNNAMED_6_QSH03001XD_I1_50: J1.50 R51.1
UNNAMED_6_QSH03001XD_I1_51: J1.51 R23.2
UNNAMED_6_QSH03001XD_I1_52: J1.52 R50.1
UNNAMED_6_QSH03001XD_I1_53: J1.53 R22.2
UNNAMED_6_QSH03001XD_I1_55: J1.55 R33.2
UNNAMED_6_QSH03001XD_I1_56: J1.56 R49.1
UNNAMED_6_QSH03001XD_I1_57: J1.57 R21.2
UNNAMED_6_QSH03001XD_I1_58: J1.58 R48.1
UNNAMED_6_QSH03001XD_I1_59: J1.59 R20.2
UNNAMED_9_BSS123_I134_D: DS3.C Q1.3(D)
UNNAMED_9_BSS123_I134_G: Q1.1(G) R116.2
UNNAMED_9_BSS123_I147_D: DS4.C Q2.3(D)
UNNAMED_9_BSS123_I147_G: Q2.1(G) R160.2
UNNAMED_9_CAPPOLARIZED_I74_1: C26.1 C27.1 D3.C F1.2 FB1.1 FB2.1
UNNAMED_9_DIODESCHOTTKY_I159_C: D1.C R77.2
UNNAMED_9_DIODESCHOTTKY_I160_C: D2.C R80.2
UNNAMED_9_FUSE_I161_1: F1.1 P6.1
UNNAMED_9_KMR2XXG_I138_2: R79.2 SW2.2
UNNAMED_9_KMR2XXG_I141_2: R72.1 R73.2 SW1.2
UNNAMED_9_KMR2XXG_I141_4: R68.1 SW1.4
UNNAMED_9_LEDS_I102_A: DS2.A R100.1
UNNAMED_9_LEDS_I105_A: DS1.A R90.1
UNNAMED_9_LEDS_I135_A: DS3.A R103.1
UNNAMED_9_LEDS_I146_A: DS4.A R117.1
UNNAMED_10_RESISTOR_I30_2: R98.2 R99.1 R101.1 R114.2
UNNAMED_10_RESISTOR_I33_2: P3.1 R99.2
UNNAMED_10_RESISTOR_I35_1: R95.1 R96.2 R112.1 R113.2
UNNAMED_10_RESISTOR_I36_2: P2.1 R95.2
UNNAMED_10_RESISTOR_I39_1: R88.2 R89.2 R92.1 R93.1
UNNAMED_10_RESISTOR_I39_2: P4.1 R92.2
UNNAMED_15_RESISTOR_I43_1: J6.16 R102.1
UNNAMED_15_RESISTOR_I44_2: J6.5 R168.2 R169.2
UNNAMED_15_RESISTOR_I45_2: J6.7 R166.2 R167.2
UNNAMED_15_RESISTOR_I46_2: J6.9 R165.2
UNNAMED_15_RESISTOR_I47_2: J6.13 R76.2
UNNAMED_15_RESISTOR_I48_2: J6.15 R164.2
UNNAMED_15_RESISTOR_I49_2: J6.17 R163.2
UNNAMED_15_RESISTOR_I50_2: J6.19 R162.2
UNNAMED_15_RESISTOR_I51_2: J5.1 R19.2
UNNAMED_15_RESISTOR_I52_2: J5.3 R24.2
UNNAMED_15_RESISTOR_I53_2: J5.5 R25.2
UNNAMED_15_RESISTOR_I54_2: J5.9 R26.2
UNNAMED_15_RESISTOR_I55_2: J5.13 R31.2
UNNAMED_15_RESISTOR_I56_2: J5.11 R18.2
UNNAMED_15_RESISTOR_I57_2: J5.17 R35.2
UNNAMED_15_RESISTOR_I58_2: J5.19 R36.2
UNNAMED_15_RESISTOR_I59_2: J5.15 R32.2
UNNAMED_15_RESISTOR_I60_1: J5.8 R9.1
UNNAMED_15_RESISTOR_I61_1: J5.10 R2.1
UNNAMED_15_RESISTOR_I62_1: J5.6 R1.1
UNNAMED_15_RESISTOR_I63_1: J5.14 R3.1 R6.1
UNNAMED_15_RESISTOR_I64_1: J5.16 R10.1
UNNAMED_15_RESISTOR_I65_1: J5.12 R4.1 R5.1
UNNAMED_15_RESISTOR_I66_1: J5.18 R8.1
UNNAMED_15_RESISTOR_I67_1: J6.6 R104.1
UNNAMED_15_RESISTOR_I68_1: J6.8 R94.1
UNNAMED_15_RESISTOR_I69_1: J6.10 R105.1
UNNAMED_15_RESISTOR_I70_1: J6.12 R106.1
UNNAMED_15_RESISTOR_I97_1: J6.18 R108.1
UNNAMED_15_RESISTOR_I98_1: J6.20 R109.1
UNNAMED_15_RESISTOR_I103_1: J6.14 R107.1
UNNAMED_17_CAPNONPOLARIZED_I130: C28.1 R121.2 R122.1 U5.10(FB2)
UNNAMED_17_CAPNONPOLARIZED_I131: C29.2 U5.7(NR/SS2)
UNNAMED_17_CAPNONPOLARIZED_I132: C44.2 U5.19(NR/SS1)
UNNAMED_17_CAPNONPOLARIZED_I133: C46.1 R131.1 R132.2 U5.16(FB1)
UNNAMED_22_CAPNONPOLARIZED_I63_: C1.2 C2.2 R37.1 U1.8(VCC)
UNNAMED_22_RESISTOR_I116_2: R42.2 U1.3(WP_N/IO2)
UNNAMED_22_RESISTOR_I117_1: R44.1 U1.6(SCK)
UNNAMED_22_RESISTOR_I118_1: R45.1 U1.5(SI/IO0)
UNNAMED_22_RESISTOR_I119_2: R39.2 U1.2(SO/IO1)
UNNAMED_22_RESISTOR_I120_1: R40.1 U1.7(HOLD_N/IO3)
UNNAMED_25_CAPNONPOLARIZED_I216: C86.2 R190.1
UNNAMED_25_CAPNONPOLARIZED_I217: C87.2 R191.1
UNNAMED_25_CAPNONPOLARIZED_I218: C88.2 R192.1
UNNAMED_25_CAPNONPOLARIZED_I219: C89.2 R193.1
UNNAMED_25_P87524BRNFRQ1ES22P_1: R145.1 U8.2(EN3)
UNNAMED_25_P87524BRNFRQ1ES22P_2: R147.1 U8.19(INT*)
UNNAMED_25_P87524BRNFRQ1ES22P_3: R143.1 U8.16(PGOOD)
